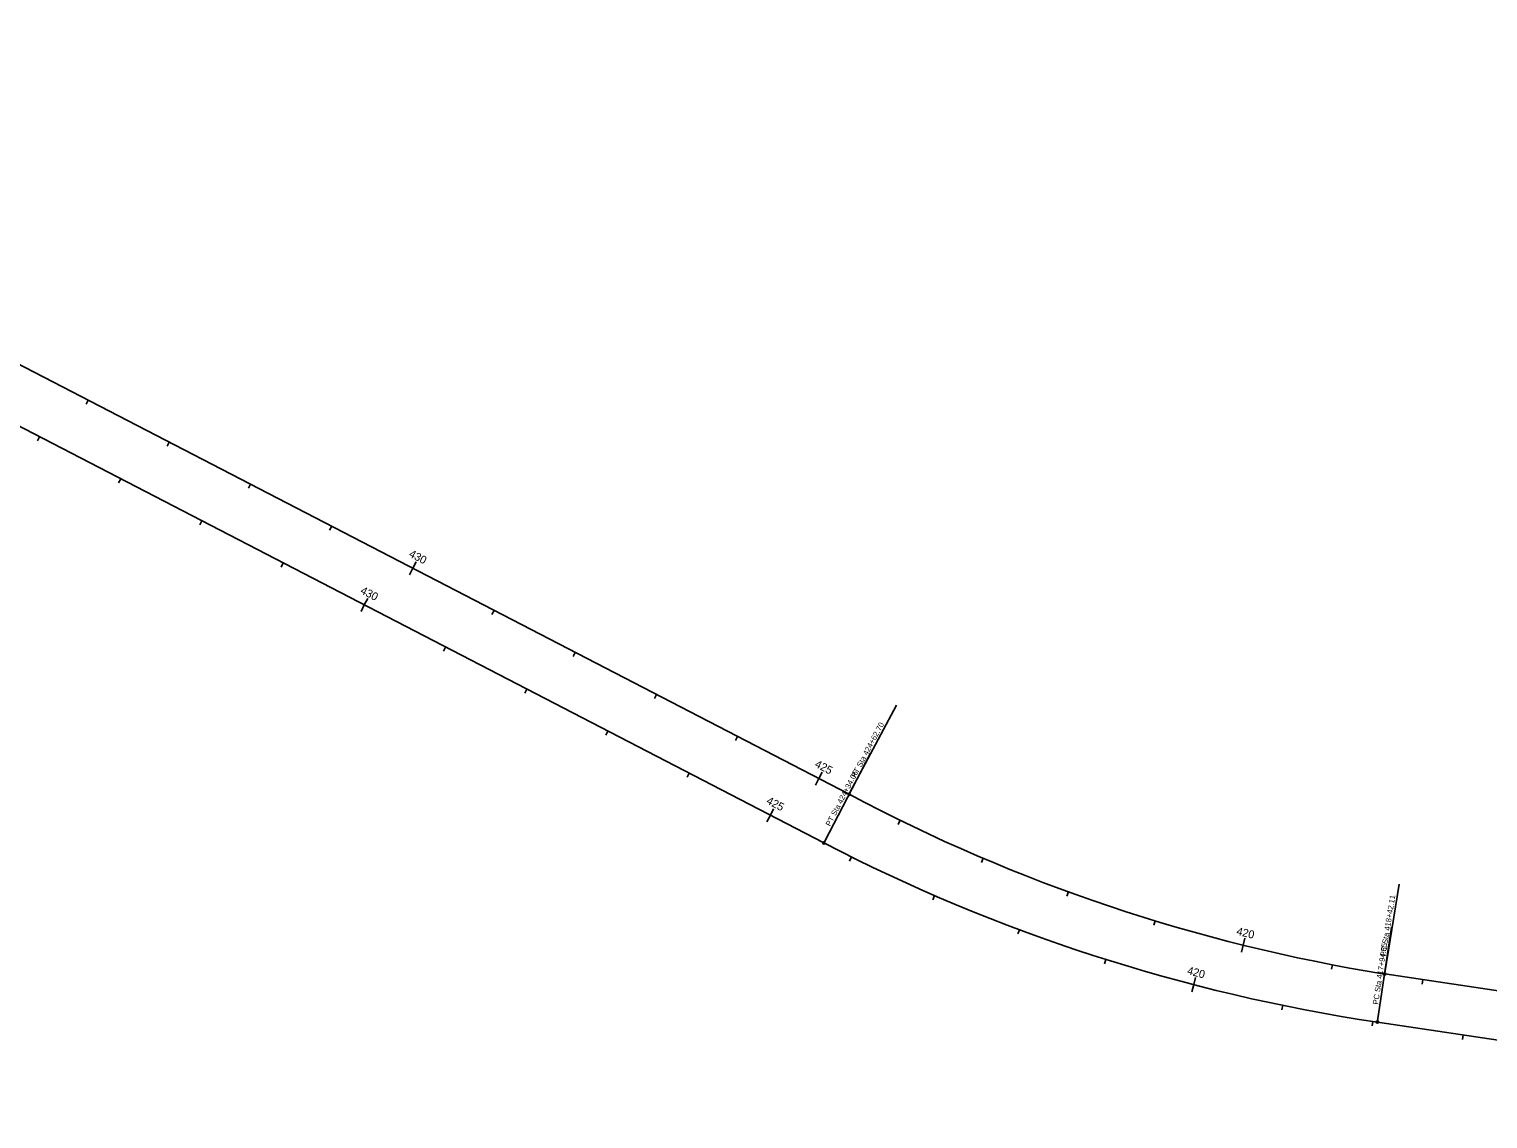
# Model space of a CAD drawing. Extents: x 1602163 to 1612907, y 1087635 to 1096265.
# Drawn here: x 1607509 to 1609104, y 1094375 to 1095567 of the extents above; entities that cross this region are included whole.
import ezdxf

# ---------------------------------------------------------------- set-up
doc = ezdxf.new("R2010")
doc.units = 0
for name, color, linetype in [('RD_HC_Cl', 7, 'Continuous'), ('RD_HC_Data_Tic', 7, 'Continuous'), ('RD_HC_Points', 7, 'Continuous'), ('RD_HC_TX_Sta50', 7, 'Continuous')]:
    doc.layers.add(name, color=color, linetype=linetype)

msp = doc.modelspace()

# ---------------------------------------------------------------- linework, layer by layer
at = {"layer": 'RD_HC_Cl'}
for p, q in [((1608405.8, 1094730), (1606790, 1095566.6)), ((1608378.1, 1094676.8), (1606762.4, 1095513.3)), ((1609716.2, 1094425.3), (1608991.5, 1094533.5)), ((1609691.8, 1094375.1), (1608983.5, 1094480.9))]:
    msp.add_line(p, q, dxfattribs=at)
for centre, radius, start, end in [((1609289.4, 1096392.5), 1882.8, 242.0082, 260.8939), ((1609270, 1096399.4), 1939.9, 242.6268, 261.5065)]:
    msp.add_arc(centre, radius, start, end, dxfattribs=at)
at = {"layer": 'RD_HC_Data_Tic'}
for p, q in [((1607573.4, 1095161), (1607571.1, 1095156.5)), ((1607520.3, 1095120.9), (1607518, 1095116.5)), ((1607662.2, 1095115), (1607659.9, 1095110.6)), ((1607609.1, 1095074.9), (1607606.8, 1095070.5)), ((1607751, 1095069), (1607748.7, 1095064.6)), ((1607697.9, 1095028.9), (1607695.6, 1095024.5)), ((1607839.8, 1095023.1), (1607837.5, 1095018.6)), ((1607786.7, 1094983), (1607784.4, 1094978.5)), ((1607928.6, 1094977.1), (1607924.9, 1094970)), ((1607928.6, 1094977.1), (1607932.3, 1094984.2)), ((1607875.5, 1094937), (1607879.2, 1094944.1)), ((1607875.5, 1094937), (1607871.9, 1094929.9)), ((1608017.4, 1094931.1), (1608015.1, 1094926.7)), ((1607964.4, 1094891), (1607962.1, 1094886.6)), ((1608106.2, 1094885.1), (1608103.9, 1094880.7)), ((1608053.2, 1094845), (1608050.9, 1094840.6)), ((1608195, 1094839.1), (1608192.7, 1094834.7)), ((1608142, 1094799.1), (1608139.7, 1094794.6)), ((1608283.8, 1094793.2), (1608281.5, 1094788.7)), ((1608230.8, 1094753.1), (1608228.5, 1094748.6)), ((1608372.6, 1094747.2), (1608376.3, 1094754.3)), ((1608372.6, 1094747.2), (1608369, 1094740.1)), ((1608319.6, 1094707.1), (1608315.9, 1094700)), ((1608319.6, 1094707.1), (1608323.2, 1094714.2)), ((1608461.6, 1094701.5), (1608459.4, 1094697)), ((1608408.5, 1094661.4), (1608406.3, 1094656.9)), ((1608552.5, 1094660), (1608550.6, 1094655.4)), ((1608645.6, 1094623.3), (1608643.9, 1094618.6)), ((1608499.2, 1094619.3), (1608497.2, 1094614.7)), ((1608740.4, 1094591.6), (1608738.9, 1094586.8)), ((1608592, 1094581.9), (1608590.2, 1094577.3)), ((1608836.8, 1094565), (1608834.9, 1094557.2)), ((1608836.8, 1094565), (1608838.7, 1094572.8)), ((1608686.5, 1094549.4), (1608685, 1094544.7)), ((1608934.4, 1094543.5), (1608933.5, 1094538.6)), ((1608782.6, 1094521.8), (1608784.6, 1094529.6)), ((1609033.1, 1094527.3), (1609032.4, 1094522.3)), ((1608782.6, 1094521.8), (1608780.6, 1094514.1)), ((1608880, 1094499.2), (1608879, 1094494.3)), ((1608978.4, 1094481.6), (1608977.7, 1094476.7)), ((1609077.3, 1094466.8), (1609076.6, 1094461.9))]:
    msp.add_line(p, q, dxfattribs=at)
at = {"layer": 'RD_HC_Points'}
for p, q in [((1608406.3, 1094731.1), (1608457.5, 1094827.4)), ((1608378.7, 1094677.9), (1608429, 1094775.1)), ((1608991.7, 1094534.7), (1609007.2, 1094631.8)), ((1608983.7, 1094482.1), (1608999, 1094584.8))]:
    msp.add_line(p, q, dxfattribs=at)
for centre in [(1608405.8, 1094730), (1608378.1, 1094676.8), (1608991.5, 1094533.5), (1608983.5, 1094480.9)]:
    msp.add_circle(centre, 1.25, dxfattribs=at)

# ---------------------------------------------------------------- texts
for s, rotation, p in [('PT Sta 424+62.70', 62.0082, (1608412.8, 1094747.5)), ('PT Sta 424+34.06', 62.6268, (1608385, 1094694.4)), ('PC Sta 418+42.11', 80.8939, (1608992.4, 1094552.3)), ('PC Sta 417+94.85', 81.5065, (1608984.3, 1094499.7))]:
    msp.add_text(s, height=6, rotation=rotation, dxfattribs=at).set_placement(p)
at = {"layer": 'RD_HC_TX_Sta50'}
for s, rotation, p in [('430', 332.6268, (1607923.5, 1094990.2)), ('430', 332.6268, (1607870.4, 1094950.1)), ('425', 332.6268, (1608367.4, 1094760.3)), ('425', 332.6268, (1608314.4, 1094720.2)), ('420', 346.0891, (1608828.8, 1094576.5)), ('420', 345.4473, (1608774.8, 1094533.4))]:
    msp.add_text(s, height=8.75, rotation=rotation, dxfattribs=at).set_placement(p)

doc.saveas('drawing.dxf')
